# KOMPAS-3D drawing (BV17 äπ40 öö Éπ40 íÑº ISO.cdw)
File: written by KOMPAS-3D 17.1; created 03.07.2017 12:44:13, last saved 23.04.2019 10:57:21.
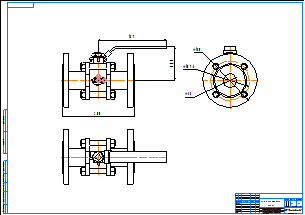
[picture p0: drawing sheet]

Sheet 1: A1, landscape

Title block, sheet 1: name: BV17 Ду40 ФФ Ру40 / без ISO; material: Внимание! Данный продукт является объектом авторского права ООО «Торговый Дом АДЛ». / Запрещается изменение, копирование, распространение / (в том числе путем копирования на другие сайты и ресурсы в Интернете) / или любое иное использование информации и объектов без предварительного / согласия правообладателя (ООО «Торговый Дом АДЛ»).; mass: 1,7; sheets: 1; organisation: ООО "Торговый дом АДЛ"; sheet format: A1; stored path: C:\Users\kka\KOMPAS_Work\!Trash\СС02 СС03 ФФ Смотровые стекла\СС01.cdw

Views: Спереди 1, Проекционный вид 2, Проекционный вид 3
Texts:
  Klimkovich
  ADL
Dimensions and other numbers on the sheet: 200; 189; 94,5; 109,8; 150; 38; 1:1; 1; 1,7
